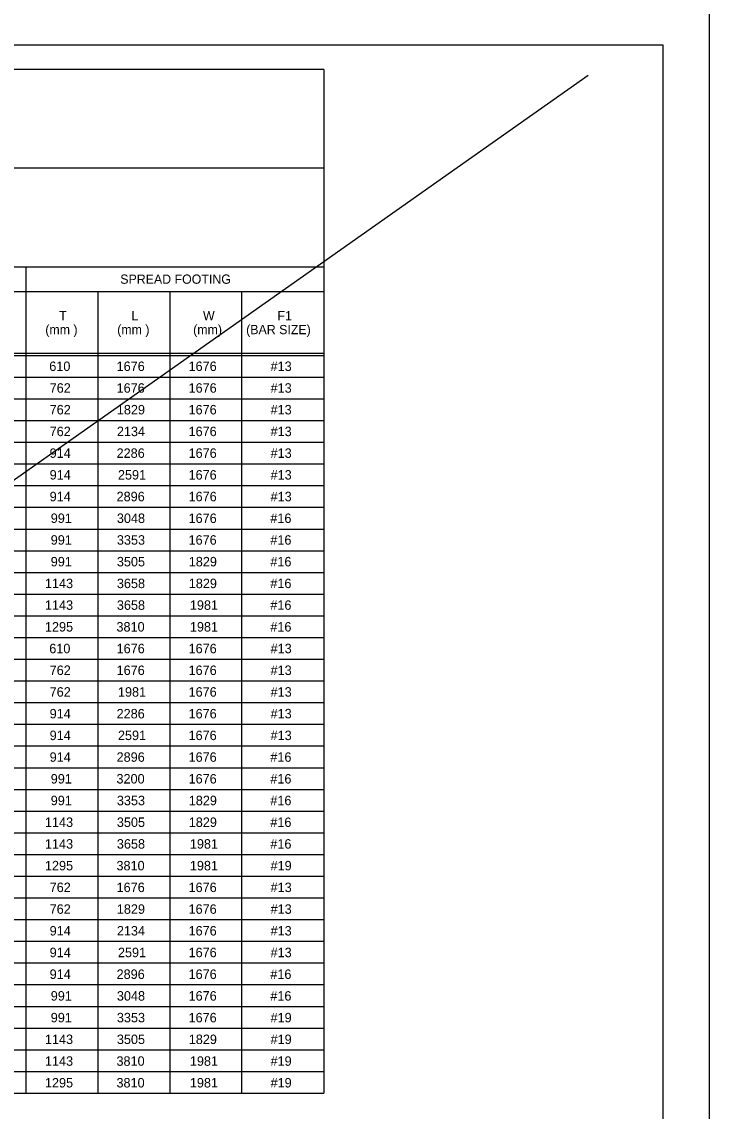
# Model space of a CAD drawing. Extents: x 3351 to 8430, y -3586 to 1457.
# Drawn here: x 7743.4 to 7966.3, y -977.3 to -623.8 of the extents above; entities that cross this region are included whole.
import ezdxf

# ---------------------------------------------------------------- set-up
doc = ezdxf.new("R2010")
doc.units = 0
for name, color, linetype in [('1', 7, 'Continuous'), ('2', 7, 'Continuous'), ('PLT-BNDY', 7, 'Continuous')]:
    doc.layers.add(name, color=color, linetype=linetype)

msp = doc.modelspace()

# ---------------------------------------------------------------- linework, layer by layer
at = {"layer": '1'}
for p, q in [((7841.34, -639.31), (7510.01, -639.31)), ((7841.34, -639.31), (7841.34, -971.42)), ((7927.1, -641.21), (7154.13, -1185.98)), ((7841.34, -671.31), (7510.01, -671.31)), ((7510.01, -703.31), (7841.34, -703.31)), ((7744.68, -703.31), (7744.68, -971.42)), ((7510.01, -711.31), (7841.34, -711.31)), ((7768.01, -711.31), (7768.01, -971.42)), ((7791.34, -711.31), (7791.34, -971.42)), ((7814.68, -711.31), (7814.68, -971.42)), ((7510.01, -731.31), (7841.34, -731.31)), ((7510.01, -732.06), (7841.34, -732.06)), ((7756.34, -735.58), (7756.34, -735.58)), ((7779.67, -735.58), (7779.67, -735.58)), ((7803.01, -735.58), (7803.01, -735.58)), ((7828, -735.58), (7828, -735.58)), ((7531.34, -739.1), (7841.34, -739.1)), ((7531.34, -746.14), (7841.34, -746.14)), ((7531.34, -753.18), (7841.34, -753.18)), ((7531.34, -760.22), (7841.34, -760.22)), ((7531.34, -767.26), (7841.34, -767.26)), ((7531.34, -774.3), (7841.34, -774.3)), ((7531.34, -781.34), (7841.34, -781.34)), ((7531.34, -788.38), (7841.34, -788.38)), ((7531.34, -795.42), (7841.34, -795.42)), ((7531.34, -802.46), (7841.34, -802.46)), ((7531.34, -809.5), (7841.34, -809.5)), ((7531.34, -816.54), (7841.34, -816.54)), ((7510.01, -823.58), (7841.34, -823.58)), ((7531.34, -830.62), (7841.34, -830.62)), ((7531.34, -837.66), (7841.34, -837.66)), ((7531.34, -844.7), (7841.34, -844.7)), ((7531.34, -851.74), (7841.34, -851.74)), ((7531.34, -858.78), (7841.34, -858.78)), ((7531.34, -865.82), (7841.34, -865.82)), ((7531.34, -872.86), (7841.34, -872.86)), ((7531.34, -879.9), (7841.34, -879.9)), ((7531.34, -886.94), (7841.34, -886.94)), ((7531.34, -893.98), (7841.34, -893.98)), ((7510.01, -901.02), (7841.34, -901.02)), ((7531.34, -908.06), (7841.34, -908.06)), ((7531.34, -915.1), (7841.34, -915.1)), ((7531.34, -922.14), (7841.34, -922.14)), ((7531.34, -929.18), (7841.34, -929.18)), ((7531.34, -936.22), (7841.34, -936.22)), ((7531.34, -943.26), (7841.34, -943.26)), ((7531.34, -950.3), (7841.34, -950.3)), ((7531.34, -957.34), (7841.34, -957.34)), ((7531.34, -964.38), (7841.34, -964.38)), ((7510.01, -971.42), (7841.34, -971.42))]:
    msp.add_line(p, q, dxfattribs=at)
at = {"layer": '2'}
for p, q in [((7165.34, -631.31), (7951.34, -631.31)), ((7951.34, -631.31), (7951.34, -1195.31))]:
    msp.add_line(p, q, dxfattribs=at)
at = {"layer": 'PLT-BNDY'}
msp.add_lwpolyline([(7125.34, -616.31), (7966.34, -616.31), (7966.34, -1210.31), (7125.34, -1210.31)], close=True, dxfattribs=at)

# ---------------------------------------------------------------- texts
at = {"layer": '1'}
for s, height, p in [('SPREAD FOOTING', 3, (7775.3, -708.81)), ('T', 3, (7755.49, -720.67)), ('L', 3, (7778.94, -720.67)), ('W', 3, (7802.14, -720.67)), ('F1', 3, (7826.3, -720.67)), ('(mm )', 3, (7750.98, -725.17)), ('(mm )', 3, (7774.31, -725.17)), ('(mm)', 3, (7798.95, -725.17)), ('(BAR SIZE)', 3, (7816.14, -725.17)), ('610', 3.07, (7752.27, -737.11)), ('1676', 3.07, (7774.11, -737.11)), ('1676', 3.07, (7797.45, -737.11)), ('#13', 3.07, (7824.06, -737.11)), ('762', 3.07, (7752.4, -744.16)), ('1676', 3.07, (7774.11, -744.16)), ('1676', 3.07, (7797.45, -744.16)), ('#13', 3.07, (7824.06, -744.16)), ('762', 3.07, (7752.4, -751.2)), ('1829', 3.07, (7774.19, -751.2)), ('1676', 3.07, (7797.45, -751.2)), ('#13', 3.07, (7824.06, -751.2)), ('762', 3.07, (7752.4, -758.25)), ('2134', 3.07, (7774.2, -758.25)), ('1676', 3.07, (7797.45, -758.25)), ('#13', 3.07, (7824.06, -758.25)), ('914', 3.07, (7752.4, -765.29)), ('2286', 3.07, (7774.11, -765.29)), ('1676', 3.07, (7797.45, -765.29)), ('#13', 3.07, (7824.06, -765.29)), ('914', 3.07, (7752.4, -772.34)), ('2591', 3.07, (7774.55, -772.34)), ('1676', 3.07, (7797.45, -772.34)), ('#13', 3.07, (7824.06, -772.34)), ('914', 3.07, (7752.4, -779.38)), ('2896', 3.07, (7774.11, -779.38)), ('1676', 3.07, (7797.45, -779.38)), ('#13', 3.07, (7824.06, -779.38)), ('991', 3.07, (7752.75, -786.42)), ('3048', 3.07, (7774.2, -786.42)), ('1676', 3.07, (7797.45, -786.42)), ('#16', 3.07, (7823.98, -786.42)), ('991', 3.07, (7752.75, -793.47)), ('3353', 3.07, (7774.2, -793.47)), ('1676', 3.07, (7797.45, -793.47)), ('#16', 3.07, (7823.98, -793.47)), ('991', 3.07, (7752.75, -800.51)), ('3505', 3.07, (7774.2, -800.51)), ('1829', 3.07, (7797.52, -800.51)), ('#16', 3.07, (7823.98, -800.51)), ('1143', 3.07, (7750.87, -807.56)), ('3658', 3.07, (7774.2, -807.56)), ('1829', 3.07, (7797.52, -807.56)), ('#16', 3.07, (7823.98, -807.56)), ('1143', 3.07, (7750.87, -814.6)), ('3658', 3.07, (7774.2, -814.6)), ('1981', 3.07, (7797.88, -814.6)), ('#16', 3.07, (7823.98, -814.6)), ('1295', 3.07, (7750.87, -821.65)), ('3810', 3.07, (7774.07, -821.65)), ('1981', 3.07, (7797.88, -821.65)), ('#16', 3.07, (7823.98, -821.65)), ('610', 3.07, (7752.27, -828.69)), ('1676', 3.07, (7774.11, -828.69)), ('1676', 3.07, (7797.45, -828.69)), ('#13', 3.07, (7824.06, -828.69)), ('762', 3.07, (7752.4, -835.74)), ('1676', 3.07, (7774.11, -835.74)), ('1676', 3.07, (7797.45, -835.74)), ('#13', 3.07, (7824.06, -835.74)), ('762', 3.07, (7752.4, -842.78)), ('1981', 3.07, (7774.55, -842.78)), ('1676', 3.07, (7797.45, -842.78)), ('#13', 3.07, (7824.06, -842.78)), ('914', 3.07, (7752.4, -849.83)), ('2286', 3.07, (7774.11, -849.83)), ('1676', 3.07, (7797.45, -849.83)), ('#13', 3.07, (7824.06, -849.82)), ('914', 3.07, (7752.4, -856.87)), ('2591', 3.07, (7774.55, -856.87)), ('1676', 3.07, (7797.45, -856.87)), ('#13', 3.07, (7824.06, -856.87)), ('914', 3.07, (7752.4, -863.91)), ('2896', 3.07, (7774.11, -863.91)), ('1676', 3.07, (7797.45, -863.91)), ('#16', 3.07, (7823.98, -863.91)), ('991', 3.07, (7752.75, -870.96)), ('3200', 3.07, (7774.07, -870.96)), ('1676', 3.07, (7797.45, -870.96)), ('#16', 3.07, (7823.98, -870.96)), ('991', 3.07, (7752.75, -878)), ('3353', 3.07, (7774.2, -878)), ('1829', 3.07, (7797.52, -878)), ('#16', 3.07, (7823.98, -878)), ('1143', 3.07, (7750.87, -885.05)), ('3505', 3.07, (7774.2, -885.05)), ('1829', 3.07, (7797.52, -885.05)), ('#16', 3.07, (7823.98, -885.05)), ('1143', 3.07, (7750.87, -892.09)), ('3658', 3.07, (7774.2, -892.09)), ('1981', 3.07, (7797.88, -892.09)), ('#16', 3.07, (7823.98, -892.09)), ('1295', 3.07, (7750.87, -899.14)), ('3810', 3.07, (7774.07, -899.14)), ('1981', 3.07, (7797.88, -899.14)), ('#19', 3.07, (7824.05, -899.14)), ('762', 3.07, (7752.4, -906.18)), ('1676', 3.07, (7774.11, -906.18)), ('1676', 3.07, (7797.45, -906.18)), ('#13', 3.07, (7824.06, -906.18)), ('762', 3.07, (7752.4, -913.23)), ('1829', 3.07, (7774.19, -913.23)), ('1676', 3.07, (7797.45, -913.23)), ('#13', 3.07, (7824.06, -913.23)), ('914', 3.07, (7752.4, -920.27)), ('2134', 3.07, (7774.2, -920.27)), ('1676', 3.07, (7797.45, -920.27)), ('#13', 3.07, (7824.06, -920.27)), ('914', 3.07, (7752.4, -927.31)), ('2591', 3.07, (7774.55, -927.31)), ('1676', 3.07, (7797.45, -927.31)), ('#13', 3.07, (7824.06, -927.31)), ('914', 3.07, (7752.4, -934.36)), ('2896', 3.07, (7774.11, -934.36)), ('1676', 3.07, (7797.45, -934.36)), ('#16', 3.07, (7823.98, -934.36)), ('991', 3.07, (7752.75, -941.4)), ('3048', 3.07, (7774.2, -941.4)), ('1676', 3.07, (7797.45, -941.4)), ('#16', 3.07, (7823.98, -941.4)), ('991', 3.07, (7752.75, -948.45)), ('3353', 3.07, (7774.2, -948.45)), ('1676', 3.07, (7797.45, -948.45)), ('#19', 3.07, (7824.05, -948.45)), ('1143', 3.07, (7750.87, -955.49)), ('3505', 3.07, (7774.2, -955.49)), ('1829', 3.07, (7797.52, -955.49)), ('#19', 3.07, (7824.05, -955.49)), ('1143', 3.07, (7750.87, -962.54)), ('3810', 3.07, (7774.07, -962.54)), ('1981', 3.07, (7797.88, -962.54)), ('#19', 3.07, (7824.05, -962.54)), ('1295', 3.07, (7750.87, -969.58)), ('3810', 3.07, (7774.07, -969.58)), ('1981', 3.07, (7797.88, -969.58)), ('#19', 3.07, (7824.05, -969.58))]:
    msp.add_text(s, height=height, dxfattribs=at).set_placement(p)

doc.saveas('drawing.dxf')
